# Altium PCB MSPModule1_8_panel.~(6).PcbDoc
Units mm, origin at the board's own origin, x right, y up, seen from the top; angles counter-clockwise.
Board outline 150 x 160 mm, 2 copper layers (Top Layer, Bottom Layer); 0 components, 0 nets, 0 pads, 0 vias.
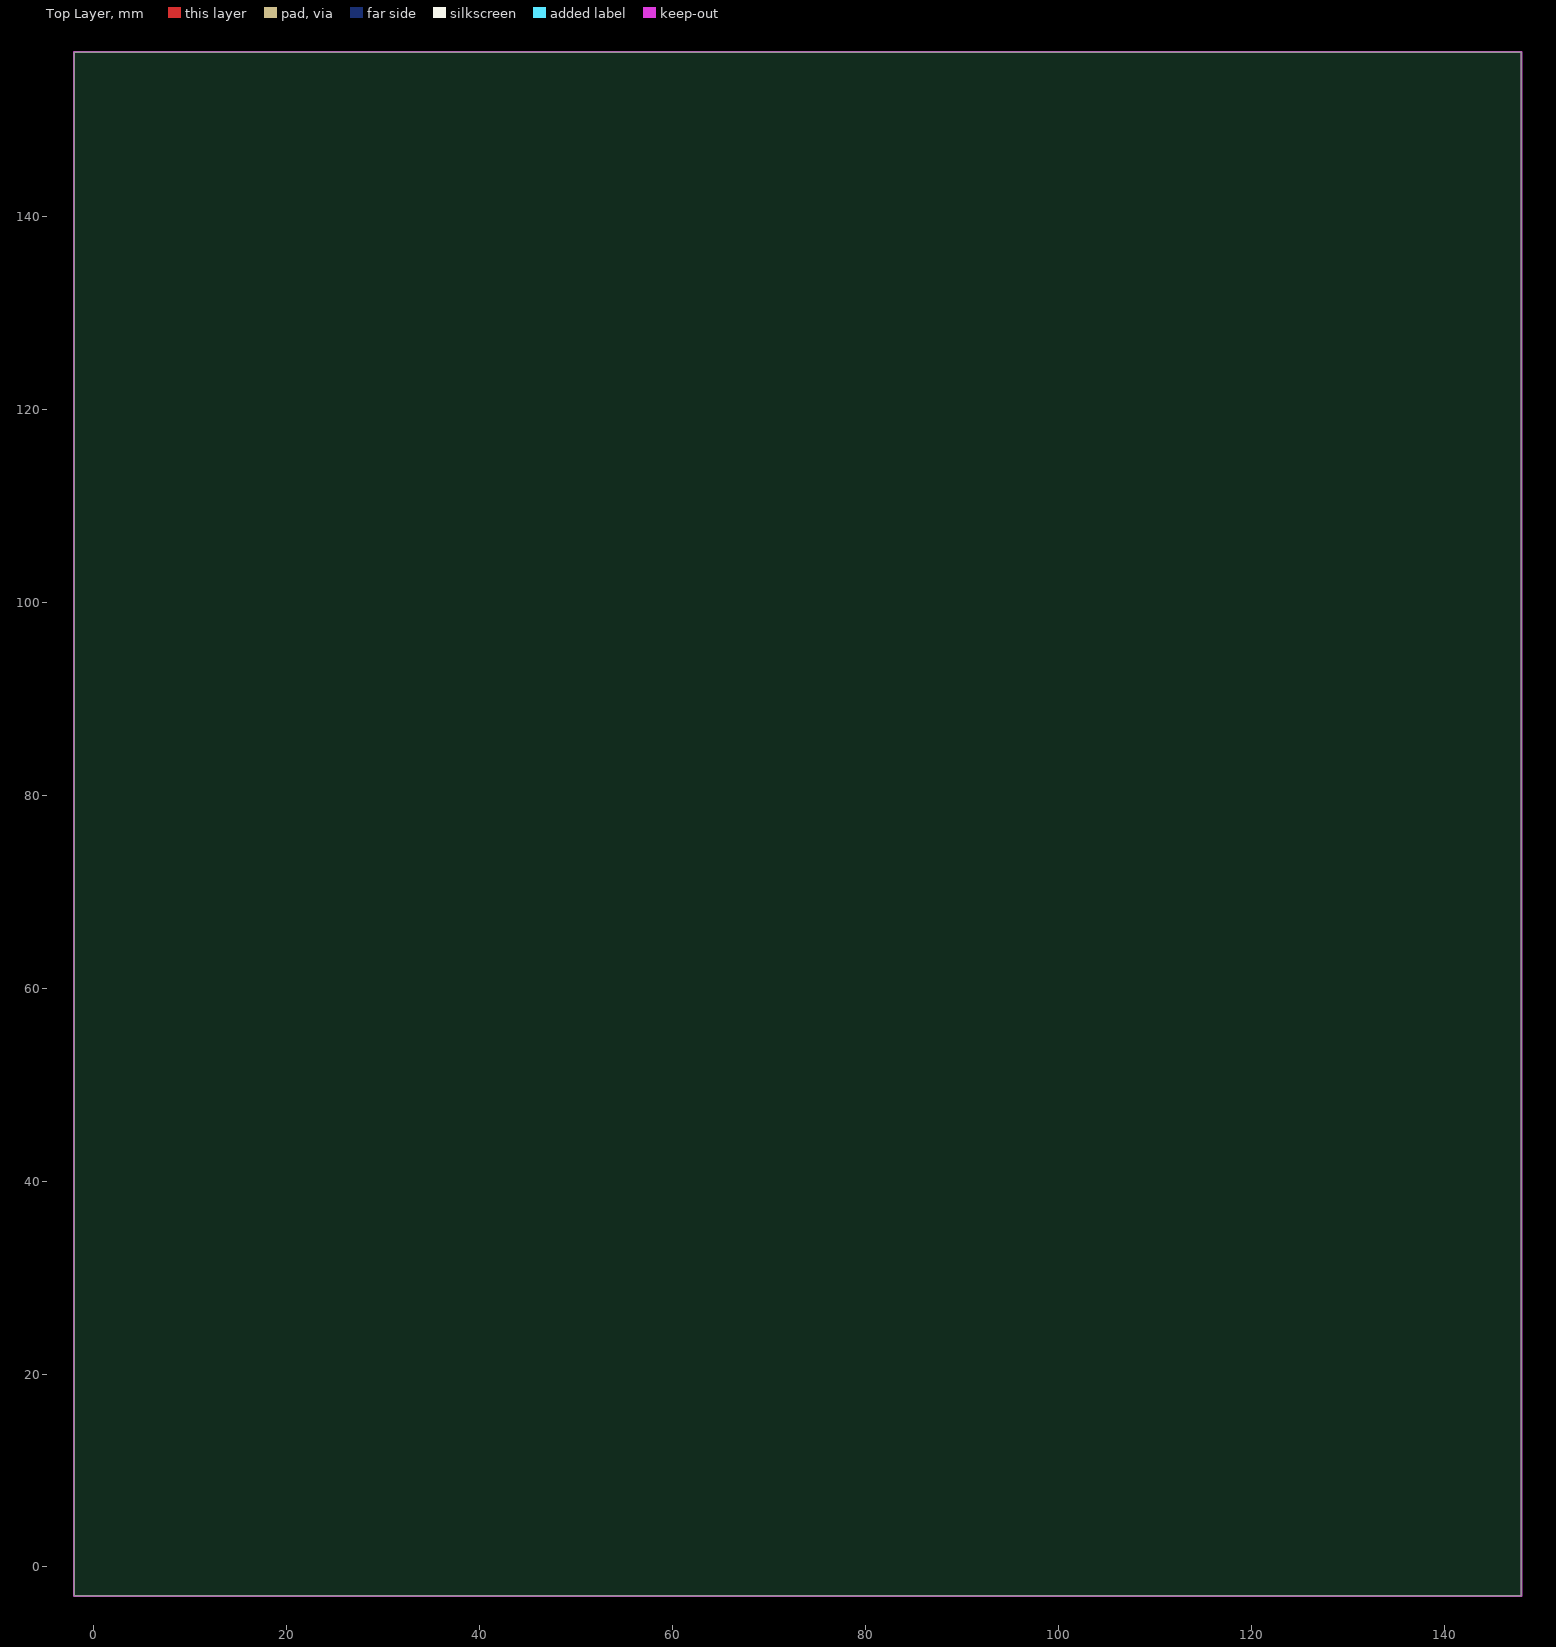
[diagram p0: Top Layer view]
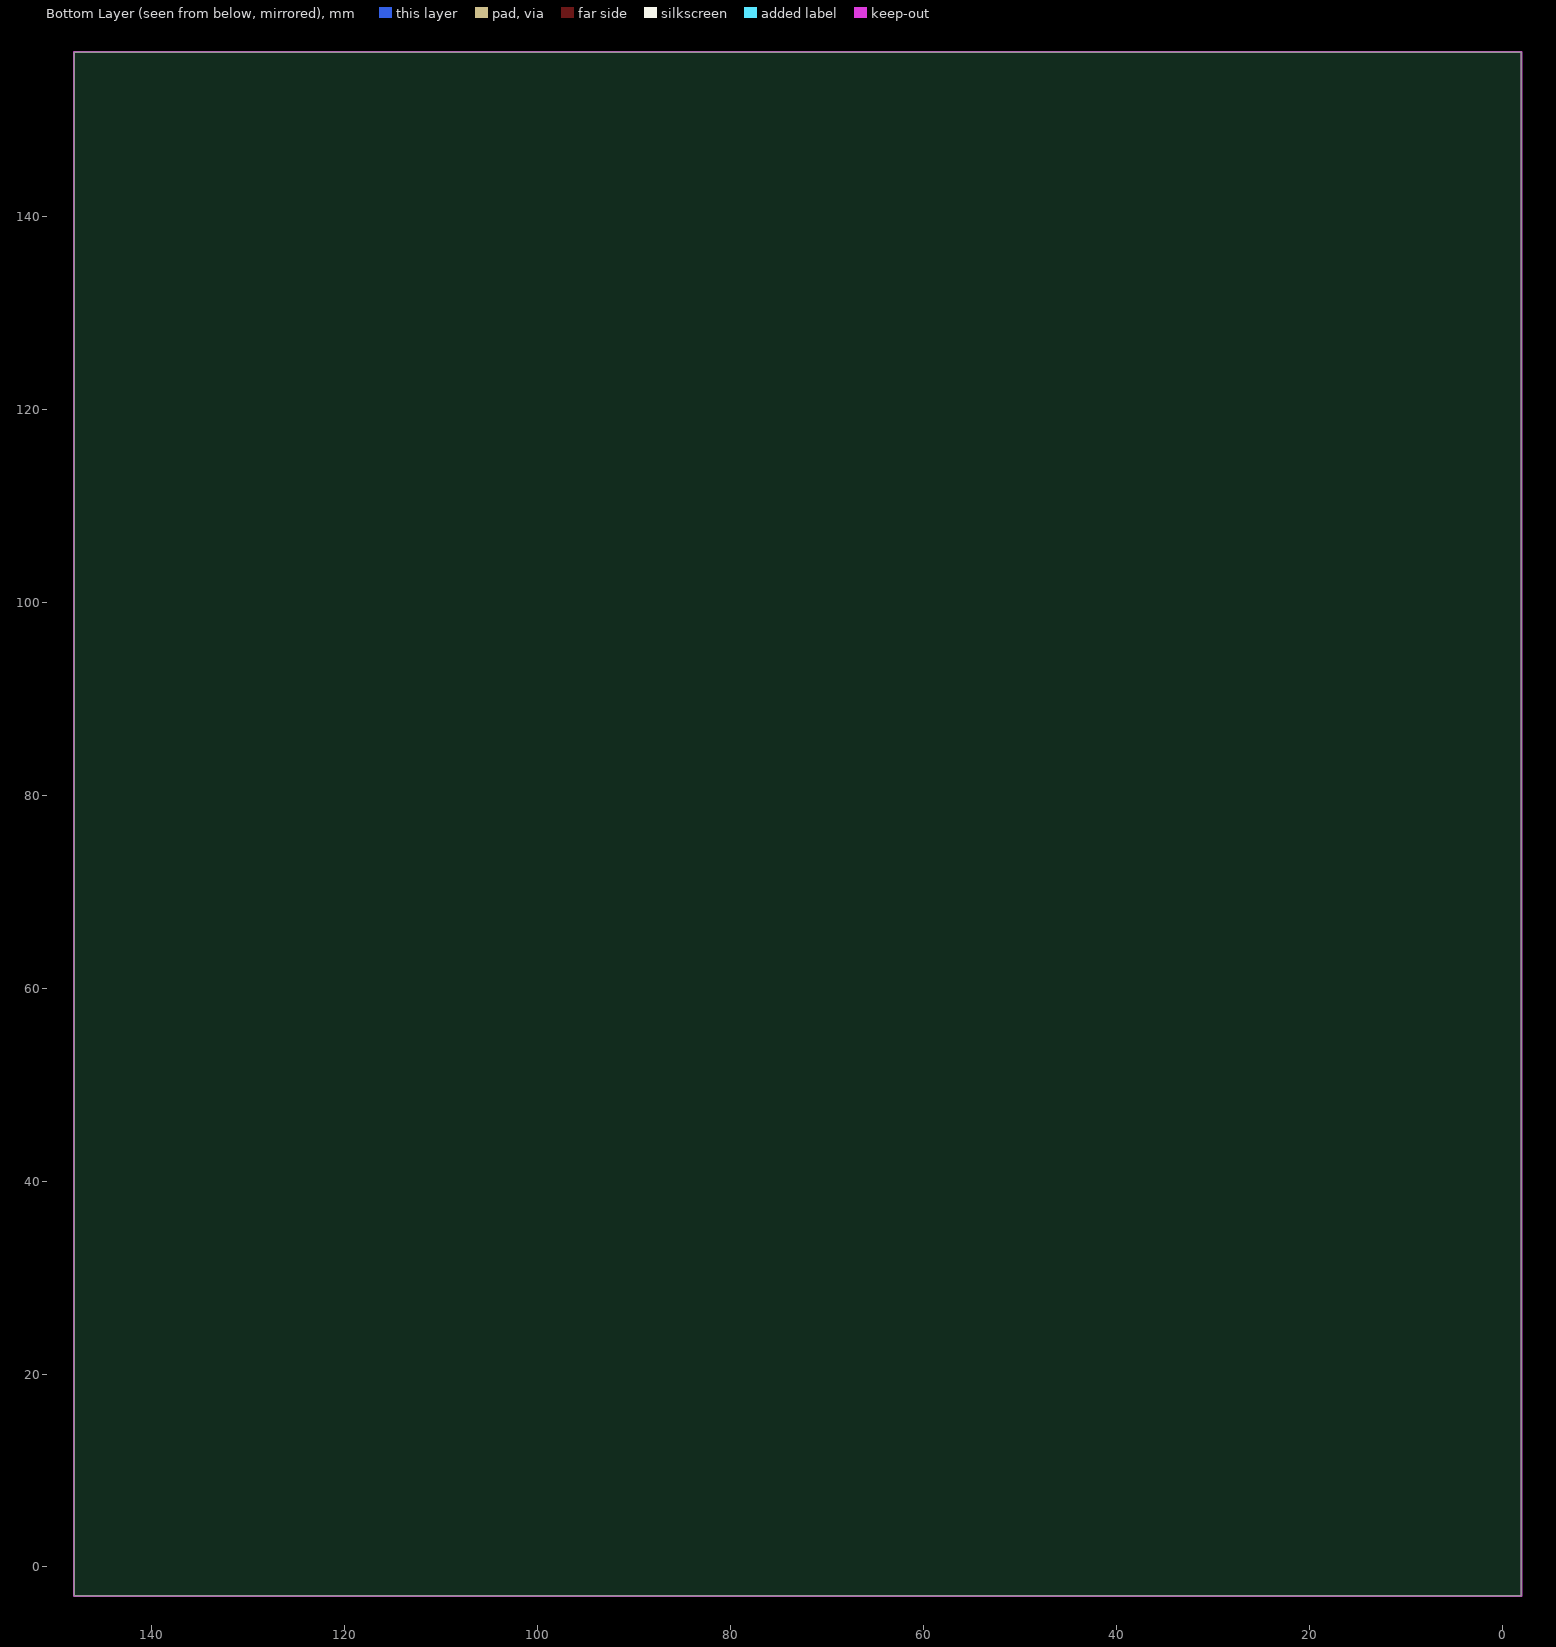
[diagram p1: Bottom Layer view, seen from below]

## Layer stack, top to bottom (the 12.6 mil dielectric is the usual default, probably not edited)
Top Solder: solder mask 0.0102, Solder Resist, Dk 3.5
Top Layer: signal copper 0.0356
Dielectric 1: dielectric 0.32, FR-4, Dk 4.8
Bottom Layer: signal copper 0.0356
Bottom Solder: solder mask 0.0102, Solder Resist, Dk 3.5

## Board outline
-2,-3 -2,157 148,157 148,-3

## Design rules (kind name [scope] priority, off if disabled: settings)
Clearance [All] p1: gap=0.254 ignorepadtopadclearanceinfootprint=FALSE except(0: Arc-Hole Track-Hole SMDPad-Hole THPad-Hole Via-Hole Fill-Hole Poly-Hole Region-Hole Text-Hole)
PolygonConnect [All] p1: connectstyle=Relief reliefconductorwidth=0.254 reliefentries=4 polygonreliefangle="90 Angle" airgapwidth=0.254
RoutingVias [All] p1: holewidth=0.711 width=1.27 viastyle="Through Hole" minholewidth=0.711 minwidth=1.27 maxholewidth=0.711 maxwidth=1.27
SolderMaskExpansion [All] p1: expansion=0.102
Width [All] p1: maxlimit=0.254 minlimit=0.254 preferedwidth=0.254
30 further rules are at their usual default settings.

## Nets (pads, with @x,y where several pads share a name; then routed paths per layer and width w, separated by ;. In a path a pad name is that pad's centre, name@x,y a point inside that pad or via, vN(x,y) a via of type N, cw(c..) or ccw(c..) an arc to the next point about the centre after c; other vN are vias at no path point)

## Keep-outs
Keep-Out Layer:
  the board outline again, w0.2

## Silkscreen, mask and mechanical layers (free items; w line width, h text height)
V-Cut:
  lines w0.2: -2,0 148,0 ; -2,50.8 148,50.8 ; -2,101.6 148,101.6 ; -2,152.4 148,152.4 ; 0,-3 0,157 ; 36.576,-3 36.576,157 ; 73.152,-3 73.152,157 ; 109.728,-3 109.728,157 ; 146.304,-3 146.304,157

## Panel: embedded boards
"MSPModule1_8.PcbDoc" at 146.304,0, 4 rows x 3 columns, spacing 36.576 x 50.8, rotation 90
